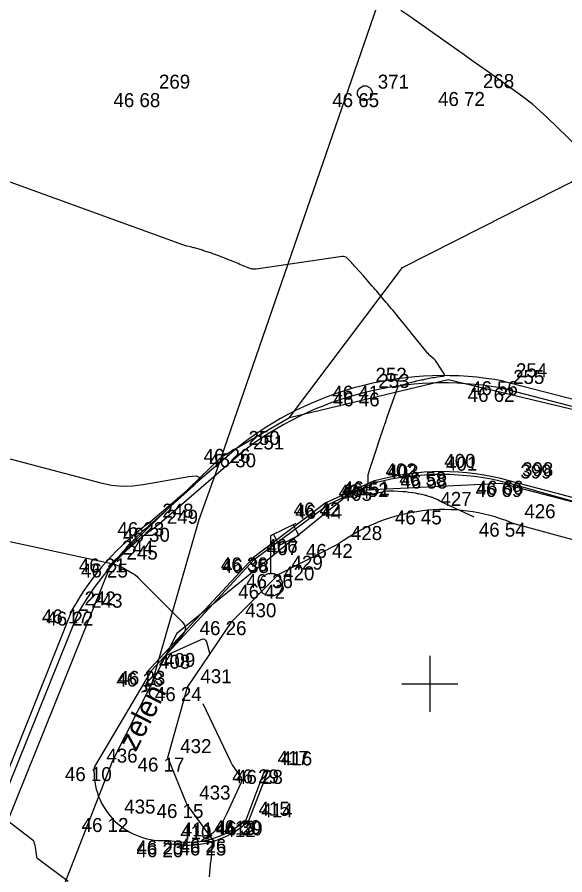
# Model space of a CAD drawing. Extents: x -702257 to -701487, y -1009871 to -1008841.
# Drawn here: x -701657.37 to -701647.59, y -1009053.42 to -1009038.08 of the extents above; entities that cross this region are included whole.
import ezdxf

# ---------------------------------------------------------------- set-up
doc = ezdxf.new("R2010")
doc.units = 0
for name, color, linetype in [('Ex_Major Contours', 7, 'Continuous'), ('Ex_Minor Contours', 7, 'Continuous'), ('Z_body', 7, 'Continuous'), ('Z_body_cisla', 7, 'Continuous'), ('Z_body_vysky_redukovane', 7, 'Continuous'), ('Z_hektometricka_sit', 7, 'Continuous'), ('Z_katastr_hranice', 7, 'Continuous'), ('Z_komunikace', 7, 'Continuous'), ('Z_obruba', 7, 'Continuous'), ('Z_popisy', 7, 'Continuous'), ('Z_site_vo_znaky', 7, 'Continuous'), ('Z_site_vodovod_znaky', 7, 'Continuous'), ('Z_zelen_obvod', 7, 'Continuous')]:
    doc.layers.add(name, color=color, linetype=linetype)

# ---------------------------------------------------------------- blocks, each defined once
blk = doc.blocks.new('POINT_DISPLAY')
blk.add_line((0, 0), (0, 0))
blk = doc.blocks.new('Z13')
for p, q in [((0, 0.88), (0.45, 1.1)), ((0.4, 1.07), (0.5, 0.88)), ((0, 0.2), (0, 0.88)), ((0.15, 0.7), (0.05, 0.9)), ((0.5, 0.88), (0.15, 0.7)), ((-0.15, 0.15), (-0.05, 0.2)), ((-0.05, 0.2), (0.05, 0.2)), ((0.05, 0.2), (0.15, 0.15)), ((-0.2, 0.05), (-0.15, 0.15)), ((-0.2, -0.05), (-0.2, 0.05)), ((0.15, 0.15), (0.2, 0.05)), ((0.2, 0.05), (0.2, -0.05)), ((-0.15, -0.15), (-0.2, -0.05)), ((-0.05, -0.2), (-0.15, -0.15)), ((0.15, -0.15), (0.05, -0.2)), ((0.2, -0.05), (0.15, -0.15)), ((0.05, -0.2), (-0.05, -0.2))]:
    blk.add_line(p, q)
blk = doc.blocks.new('Z614')
for p, q in [((-0.13, 0.03), (-0.1, 0.08)), ((-0.13, -0.03), (-0.13, 0.03)), ((-0.1, 0.08), (-0.08, 0.1)), ((-0.08, 0.1), (-0.03, 0.13)), ((-0.03, 0.13), (0.03, 0.13)), ((0.03, 0.13), (0.08, 0.1)), ((0.08, 0.1), (0.1, 0.08)), ((0.1, 0.08), (0.13, 0.03)), ((0.13, 0.03), (0.13, -0.03)), ((-0.1, -0.08), (-0.13, -0.03)), ((-0.08, -0.1), (-0.1, -0.08)), ((-0.03, -0.13), (-0.08, -0.1)), ((0.03, -0.13), (-0.03, -0.13)), ((0.08, -0.1), (0.03, -0.13)), ((0.1, -0.08), (0.08, -0.1)), ((0.13, -0.03), (0.1, -0.08))]:
    blk.add_line(p, q)

msp = doc.modelspace()

# ---------------------------------------------------------------- linework, layer by layer
at = {"layer": 'Ex_Major Contours'}
msp.add_lwpolyline([(-701656.465, -1009053.532), (-701657.004, -1009053.131), (-701657.012, -1009053.124), (-701657.018, -1009053.115), (-701657.023, -1009053.105), (-701657.025, -1009053.094), (-701657.03, -1009053.044), (-701657.031, -1009053.034), (-701657.032, -1009053.023), (-701657.034, -1009053.013), (-701657.035, -1009053.003), (-701657.042, -1009052.958), (-701657.043, -1009052.95), (-701657.044, -1009052.941), (-701657.046, -1009052.932), (-701657.048, -1009052.924), (-701657.055, -1009052.886), (-701657.058, -1009052.872), (-701657.062, -1009052.858), (-701657.069, -1009052.831), (-701657.072, -1009052.824), (-701657.075, -1009052.818), (-701657.079, -1009052.813), (-701657.084, -1009052.808), (-701657.686, -1009052.349)], dxfattribs=at)
at = {"layer": 'Ex_Minor Contours'}
for points in [[(-701646.975, -1009040.775), (-701647.911, -1009039.87), (-701648.034, -1009039.756), (-701648.161, -1009039.646), (-701648.292, -1009039.541), (-701648.427, -1009039.441), (-701648.974, -1009039.049), (-701649.111, -1009038.952), (-701649.248, -1009038.854), (-701649.385, -1009038.757), (-701649.522, -1009038.659), (-701650.336, -1009038.083), (-701650.519, -1009037.965)], [(-701649.207, -1009047.022), (-701649.797, -1009046.746), (-701649.805, -1009046.742), (-701649.812, -1009046.738), (-701649.82, -1009046.734), (-701649.827, -1009046.73), (-701649.857, -1009046.714), (-701649.864, -1009046.71), (-701649.871, -1009046.706), (-701649.879, -1009046.702), (-701649.887, -1009046.699), (-701649.932, -1009046.68), (-701649.942, -1009046.675), (-701649.952, -1009046.671), (-701649.963, -1009046.668), (-701649.973, -1009046.664), (-701650.036, -1009046.644), (-701650.05, -1009046.64), (-701650.064, -1009046.636), (-701650.078, -1009046.632), (-701650.093, -1009046.629), (-701650.179, -1009046.609), (-701650.199, -1009046.605), (-701650.218, -1009046.602), (-701650.237, -1009046.598), (-701650.257, -1009046.595), (-701650.377, -1009046.578), (-701650.403, -1009046.575), (-701650.43, -1009046.571), (-701650.456, -1009046.569), (-701650.483, -1009046.567), (-701650.646, -1009046.555), (-701650.682, -1009046.554), (-701650.718, -1009046.555), (-701650.754, -1009046.558), (-701650.79, -1009046.564), (-701651.083, -1009046.621), (-701651.099, -1009046.622), (-701651.114, -1009046.619), (-701651.127, -1009046.611), (-701651.138, -1009046.598), (-701651.184, -1009046.528), (-701651.189, -1009046.518), (-701651.19, -1009046.508), (-701651.187, -1009046.499), (-701651.18, -1009046.491), (-701651.131, -1009046.445), (-701651.123, -1009046.438), (-701651.109, -1009046.427), (-701651.106, -1009046.424), (-701651.105, -1009046.422), (-701651.104, -1009046.418), (-701651.103, -1009046.415), (-701651.103, -1009046.278), (-701651.103, -1009046.273), (-701651.102, -1009046.268), (-701651.101, -1009046.263), (-701651.1, -1009046.259), (-701651.092, -1009046.231), (-701651.089, -1009046.222), (-701651.077, -1009046.183), (-701651.07, -1009046.162), (-701651.047, -1009046.09), (-701651.035, -1009046.054), (-701650.935, -1009045.749), (-701650.923, -1009045.712), (-701650.911, -1009045.675), (-701650.899, -1009045.638), (-701650.886, -1009045.601), (-701650.828, -1009045.431), (-701650.82, -1009045.406), (-701650.811, -1009045.381), (-701650.803, -1009045.356), (-701650.794, -1009045.331), (-701650.759, -1009045.232), (-701650.741, -1009045.182), (-701650.724, -1009045.132), (-701650.571, -1009044.697), (-701650.565, -1009044.681), (-701650.563, -1009044.678), (-701650.561, -1009044.677), (-701650.373, -1009044.622), (-701650.35, -1009044.616), (-701650.327, -1009044.61), (-701650.281, -1009044.598), (-701650.269, -1009044.595), (-701650.258, -1009044.592), (-701650.246, -1009044.589), (-701650.235, -1009044.586), (-701650.155, -1009044.568), (-701650.138, -1009044.565), (-701650.121, -1009044.561), (-701650.104, -1009044.557), (-701650.087, -1009044.554), (-701649.949, -1009044.527), (-701649.936, -1009044.524), (-701649.923, -1009044.522), (-701649.889, -1009044.516), (-701649.869, -1009044.513), (-701649.761, -1009044.498), (-701649.744, -1009044.494), (-701649.736, -1009044.485), (-701649.735, -1009044.474), (-701649.742, -1009044.458), (-701649.872, -1009044.258), (-701649.884, -1009044.24), (-701649.898, -1009044.223), (-701649.912, -1009044.207), (-701649.928, -1009044.192), (-701649.993, -1009044.134), (-701650.009, -1009044.12), (-701650.024, -1009044.104), (-701650.038, -1009044.088), (-701650.052, -1009044.072), (-701650.332, -1009043.724), (-701650.37, -1009043.677), (-701650.409, -1009043.629), (-701650.448, -1009043.582), (-701650.486, -1009043.535), (-701650.657, -1009043.328), (-701650.688, -1009043.29), (-701650.72, -1009043.252), (-701650.751, -1009043.214), (-701650.783, -1009043.176), (-701650.923, -1009043.011), (-701650.949, -1009042.98), (-701650.975, -1009042.95), (-701651.001, -1009042.92), (-701651.027, -1009042.889), (-701651.185, -1009042.708), (-701651.187, -1009042.706), (-701651.327, -1009042.551), (-701651.346, -1009042.531), (-701651.364, -1009042.511), (-701651.383, -1009042.491), (-701651.401, -1009042.471), (-701651.476, -1009042.392), (-701651.496, -1009042.375), (-701651.518, -1009042.364), (-701651.542, -1009042.359), (-701651.567, -1009042.36), (-701653.104, -1009042.585), (-701653.141, -1009042.588), (-701653.177, -1009042.585), (-701653.212, -1009042.578), (-701653.247, -1009042.566), (-701653.393, -1009042.501), (-701653.423, -1009042.489), (-701653.453, -1009042.476), (-701653.482, -1009042.464), (-701653.512, -1009042.452), (-701653.64, -1009042.4), (-701653.665, -1009042.39), (-701653.691, -1009042.38), (-701653.717, -1009042.37), (-701653.743, -1009042.36), (-701653.854, -1009042.32), (-701653.877, -1009042.311), (-701653.899, -1009042.304), (-701653.922, -1009042.296), (-701653.945, -1009042.288), (-701654.042, -1009042.257), (-701654.062, -1009042.25), (-701654.081, -1009042.244), (-701654.101, -1009042.238), (-701654.121, -1009042.232), (-701654.206, -1009042.208), (-701654.223, -1009042.203), (-701654.24, -1009042.199), (-701654.258, -1009042.195), (-701654.275, -1009042.19), (-701654.345, -1009042.174), (-701654.362, -1009042.17), (-701654.38, -1009042.165), (-701654.397, -1009042.159), (-701654.414, -1009042.153), (-701658.244, -1009040.763)], [(-701660.105, -1009045.292), (-701655.877, -1009046.408), (-701655.689, -1009046.447), (-701655.5, -1009046.465), (-701655.31, -1009046.463), (-701655.12, -1009046.439), (-701654.306, -1009046.295), (-701654.176, -1009046.284), (-701654.119, -1009046.308), (-701654.135, -1009046.367), (-701654.224, -1009046.462), (-701654.96, -1009047.123), (-701654.977, -1009047.139), (-701654.994, -1009047.154), (-701655.028, -1009047.185), (-701655.036, -1009047.193), (-701655.045, -1009047.201), (-701655.054, -1009047.208), (-701655.062, -1009047.216), (-701655.147, -1009047.285), (-701655.16, -1009047.296), (-701655.173, -1009047.307), (-701655.185, -1009047.319), (-701655.196, -1009047.331), (-701655.245, -1009047.381), (-701655.255, -1009047.392), (-701655.266, -1009047.403), (-701655.277, -1009047.414), (-701655.288, -1009047.425), (-701655.333, -1009047.467), (-701655.345, -1009047.478), (-701655.355, -1009047.489), (-701655.366, -1009047.5), (-701655.376, -1009047.512), (-701655.471, -1009047.625), (-701655.481, -1009047.636), (-701655.491, -1009047.648), (-701655.513, -1009047.671), (-701655.518, -1009047.677), (-701655.523, -1009047.683), (-701655.528, -1009047.689), (-701655.533, -1009047.695), (-701655.65, -1009047.849), (-701655.65, -1009047.853), (-701655.502, -1009047.918), (-701655.478, -1009047.929), (-701655.454, -1009047.941), (-701655.43, -1009047.954), (-701655.406, -1009047.967), (-701655.306, -1009048.027), (-701655.282, -1009048.042), (-701655.26, -1009048.059), (-701655.238, -1009048.077), (-701655.217, -1009048.097), (-701654.423, -1009048.893), (-701654.382, -1009048.947), (-701654.367, -1009049.001), (-701654.377, -1009049.057), (-701654.413, -1009049.114), (-701654.689, -1009049.447), (-701654.698, -1009049.458), (-701654.707, -1009049.469), (-701654.725, -1009049.492), (-701654.728, -1009049.497), (-701654.728, -1009049.499), (-701654.725, -1009049.499), (-701654.72, -1009049.497), (-701654.083, -1009049.208), (-701654.051, -1009049.199), (-701654.025, -1009049.203), (-701654.006, -1009049.22), (-701653.993, -1009049.25), (-701653.93, -1009049.47)], [(-701654.054, -1009050.354), (-701653.56, -1009051.391), (-701653.542, -1009051.425), (-701653.524, -1009051.458), (-701653.503, -1009051.49), (-701653.482, -1009051.522), (-701653.392, -1009051.645), (-701653.374, -1009051.677), (-701653.366, -1009051.709), (-701653.368, -1009051.742), (-701653.379, -1009051.777), (-701653.629, -1009052.319), (-701653.64, -1009052.343), (-701653.651, -1009052.367), (-701653.674, -1009052.415), (-701653.68, -1009052.426), (-701653.686, -1009052.438), (-701653.693, -1009052.449), (-701653.7, -1009052.46), (-701653.735, -1009052.513), (-701653.743, -1009052.525), (-701653.752, -1009052.537), (-701653.761, -1009052.549), (-701653.771, -1009052.56), (-701653.819, -1009052.613), (-701653.831, -1009052.626), (-701653.843, -1009052.637), (-701653.855, -1009052.649), (-701653.868, -1009052.66), (-701653.932, -1009052.712), (-701653.947, -1009052.723), (-701653.963, -1009052.735), (-701653.979, -1009052.745), (-701653.995, -1009052.755), (-701654.074, -1009052.802), (-701654.082, -1009052.807), (-701654.084, -1009052.811), (-701654.08, -1009052.813), (-701654.071, -1009052.814), (-701654.016, -1009052.813), (-701654.006, -1009052.813), (-701653.996, -1009052.813), (-701653.986, -1009052.814), (-701653.976, -1009052.814), (-701653.917, -1009052.819), (-701653.909, -1009052.819), (-701653.89, -1009052.819), (-701653.89, -1009052.82), (-701653.91, -1009053.124), (-701653.911, -1009053.133), (-701653.912, -1009053.141), (-701653.913, -1009053.15), (-701653.915, -1009053.159), (-701653.921, -1009053.194), (-701653.922, -1009053.203), (-701653.923, -1009053.212), (-701653.925, -1009053.221), (-701653.925, -1009053.23), (-701653.945, -1009053.453)]]:
    msp.add_lwpolyline(points, dxfattribs=at)
at = {"layer": 'Z_hektometricka_sit'}
for p, q in [((-701650, -1009049.5), (-701650, -1009050.5)), ((-701650, -1009049.5), (-701650, -1009050.5)), ((-701650.5, -1009050), (-701649.5, -1009050)), ((-701650.5, -1009050), (-701649.5, -1009050))]:
    msp.add_line(p, q, dxfattribs=at)
at = {"layer": 'Z_katastr_hranice'}
for p, q in [((-701653.72, -1009045.94), (-701645.42, -1009021.86)), ((-701650.49, -1009042.56), (-701647.04, -1009040.81)), ((-701652.51, -1009045.24), (-701650.49, -1009042.56)), ((-701652.51, -1009045.24), (-701649.67, -1009044.56)), ((-701649.67, -1009044.56), (-701641.86, -1009046.44)), ((-701653.72, -1009045.94), (-701652.51, -1009045.24)), ((-701666.43, -1009045.51), (-701655.69, -1009047.85)), ((-701655.69, -1009047.85), (-701653.72, -1009045.94)), ((-701653.72, -1009045.94), (-701654.13, -1009047.07)), ((-701648.72, -1009046.42), (-701651.37, -1009046.55)), ((-701642.28, -1009048.09), (-701648.72, -1009046.42)), ((-701651.37, -1009046.55), (-701654.52, -1009049.1)), ((-701654.13, -1009047.07), (-701654.97, -1009049.99)), ((-701664.86, -1009070.6), (-701655.69, -1009047.85)), ((-701654.52, -1009049.1), (-701654.97, -1009049.99)), ((-701654.97, -1009049.99), (-701655.67, -1009051.38)), ((-701655.67, -1009051.38), (-701657.22, -1009055.35))]:
    msp.add_line(p, q, dxfattribs=at)
at = {"layer": 'Z_komunikace'}
for p, q in [((-701648.68, -1009044.59), (-701641.92, -1009046.35)), ((-701653.46, -1009045.8), (-701655, -1009047.11)), ((-701656.39, -1009048.67), (-701658.88, -1009054.88))]:
    msp.add_line(p, q, dxfattribs=at)
for centre, major_axis, ratio, start_param, end_param in [((-701649.752, -1009050.4), (-1.421, 5.737), 0.998154, 5.85723, 6.719509), ((-701652.145, -1009051.04), (-4.378, -2.134), 0.997151, 4.886498, 5.319013)]:
    msp.add_ellipse(centre, major_axis=major_axis, ratio=ratio, start_param=start_param, end_param=end_param, dxfattribs=at)
at = {"layer": 'Z_obruba'}
for p, q in [((-701641.95, -1009046.47), (-701648.74, -1009044.71)), ((-701654.92, -1009047.21), (-701653.38, -1009045.88)), ((-701651.85, -1009046.76), (-701651.01, -1009046.38)), ((-701650.99, -1009046.41), (-701651.82, -1009046.8)), ((-701648.6, -1009046.41), (-701646.83, -1009046.91)), ((-701646.81, -1009046.84), (-701648.58, -1009046.37)), ((-701651.85, -1009046.76), (-701653.15, -1009047.74)), ((-701653.13, -1009047.77), (-701651.82, -1009046.8)), ((-701653.15, -1009047.74), (-701655.06, -1009049.8)), ((-701654.98, -1009049.77), (-701653.13, -1009047.77)), ((-701658.79, -1009054.94), (-701656.27, -1009048.71)), ((-701654.98, -1009049.77), (-701656, -1009051.49)), ((-701655.06, -1009049.8), (-701654.98, -1009049.77)), ((-701652.95, -1009051.53), (-701653.29, -1009052.44)), ((-701653.24, -1009052.46), (-701652.88, -1009051.54)), ((-701654.68, -1009052.85), (-701654.66, -1009052.8))]:
    msp.add_line(p, q, dxfattribs=at)
for centre, major_axis, ratio, start_param, end_param in [((-701649.751, -1009050.494), (-1.031, 5.782), 0.99776, 5.933119, 6.774216), ((-701649.769, -1009050.679), (-2.027, 3.989), 0.997622, 5.542645, 6.09371), ((-701649.827, -1009051.003), (-3.857, -2.802), 0.992757, 3.826656, 4.334624), ((-701652.38, -1009050.878), (-1.6, -4.185), 0.993971, 4.115383, 4.570102), ((-701654.772, -1009051.566), (0.197, -1.223), 0.993274, 4.492315, 6.213696), ((-701654.346, -1009051.225), (-0.089, -1.657), 0.997989, 6.133484, 7.06771), ((-701654.338, -1009051.251), (1.311, -0.891), 0.997858, 5.103635, 6.031122)]:
    msp.add_ellipse(centre, major_axis=major_axis, ratio=ratio, start_param=start_param, end_param=end_param, dxfattribs=at)
at = {"layer": 'Z_zelen_obvod'}
for p, q in [((-701648.54, -1009047.12), (-701646.62, -1009047.65)), ((-701652.7, -1009048.04), (-701651.63, -1009047.5)), ((-701653.53, -1009048.88), (-701652.7, -1009048.04)), ((-701654.33, -1009050.06), (-701653.53, -1009048.88)), ((-701654.68, -1009051.32), (-701654.33, -1009050.06)), ((-701654.34, -1009052.15), (-701654.68, -1009051.32)), ((-701653.89, -1009052.77), (-701654.34, -1009052.15))]:
    msp.add_line(p, q, dxfattribs=at)
msp.add_ellipse((-701649.753, -1009050.08), major_axis=(-2.726, -1.684), ratio=0.995771, start_param=3.772026, end_param=4.787538, dxfattribs=at)

# ---------------------------------------------------------------- block references
at = {"layer": 'Z_body'}
for p in [(-701655.07, -1009039.44), (-701651.16, -1009039.44), (-701649.27, -1009039.42), (-701651.2, -1009044.67), (-701648.74, -1009044.71), (-701648.68, -1009044.59), (-701651.15, -1009044.79), (-701653.46, -1009045.8), (-701653.38, -1009045.88), (-701649.96, -1009046.21), (-701649.94, -1009046.26), (-701651.01, -1009046.38), (-701650.99, -1009046.41), (-701648.6, -1009046.41), (-701648.58, -1009046.37), (-701651.85, -1009046.76), (-701651.82, -1009046.8), (-701650.04, -1009046.9), (-701655, -1009047.11), (-701648.54, -1009047.12), (-701654.92, -1009047.21), (-701651.63, -1009047.5), (-701655.73, -1009047.76), (-701653.15, -1009047.74), (-701653.13, -1009047.77), (-701655.65, -1009047.85), (-701652.7, -1009048.04), (-701652.84, -1009048.23), (-701656.39, -1009048.67), (-701656.27, -1009048.71), (-701653.53, -1009048.88), (-701654.98, -1009049.77), (-701655.06, -1009049.8), (-701654.33, -1009050.06), (-701654.68, -1009051.32), (-701656, -1009051.49), (-701652.95, -1009051.53), (-701652.88, -1009051.54), (-701654.34, -1009052.15), (-701655.68, -1009052.4), (-701653.29, -1009052.44), (-701653.24, -1009052.46), (-701654.68, -1009052.85), (-701654.66, -1009052.8), (-701653.89, -1009052.77), (-701653.89, -1009052.82)]:
    msp.add_blockref('POINT_DISPLAY', p, dxfattribs=at)
at = {"layer": 'Z_site_vo_znaky'}
msp.add_blockref('Z13', (-701652.84, -1009048.23), dxfattribs=at)
at = {"layer": 'Z_site_vodovod_znaky'}
msp.add_blockref('Z614', (-701651.16, -1009039.44), dxfattribs=at)

# ---------------------------------------------------------------- texts
at = {"layer": 'Z_body_cisla'}
for s, p in [('269', (-701654.84, -1009039.36)), ('371', (-701650.93, -1009039.36)), ('268', (-701649.05, -1009039.35)), ('254', (-701648.46, -1009044.52)), ('252', (-701650.97, -1009044.6)), ('255', (-701648.51, -1009044.64)), ('253', (-701650.92, -1009044.71)), ('250', (-701653.24, -1009045.73)), ('251', (-701653.16, -1009045.81)), ('400', (-701649.74, -1009046.14)), ('401', (-701649.71, -1009046.19)), ('402', (-701650.79, -1009046.31)), ('403', (-701650.76, -1009046.33)), ('399', (-701648.38, -1009046.33)), ('398', (-701648.35, -1009046.29)), ('404', (-701651.63, -1009046.69)), ('405', (-701651.59, -1009046.73)), ('427', (-701649.81, -1009046.82)), ('248', (-701654.78, -1009047.03)), ('426', (-701648.31, -1009047.04)), ('249', (-701654.7, -1009047.14)), ('428', (-701651.41, -1009047.43)), ('244', (-701655.5, -1009047.69)), ('406', (-701652.92, -1009047.66)), ('407', (-701652.91, -1009047.7)), ('245', (-701655.42, -1009047.78)), ('429', (-701652.47, -1009047.96)), ('420', (-701652.62, -1009048.15)), ('242', (-701656.17, -1009048.6)), ('243', (-701656.05, -1009048.64)), ('430', (-701653.3, -1009048.81)), ('408', (-701654.84, -1009049.73)), ('409', (-701654.75, -1009049.7)), ('431', (-701654.1, -1009049.99)), ('432', (-701654.46, -1009051.24)), ('436', (-701655.78, -1009051.41)), ('417', (-701652.72, -1009051.45)), ('416', (-701652.66, -1009051.46)), ('433', (-701654.12, -1009052.07)), ('435', (-701655.46, -1009052.32)), ('415', (-701653.06, -1009052.36)), ('414', (-701653.01, -1009052.39)), ('410', (-701654.46, -1009052.78)), ('411', (-701654.43, -1009052.73)), ('413', (-701653.67, -1009052.7)), ('412', (-701653.67, -1009052.74))]:
    msp.add_text(s, height=0.25, dxfattribs=at).set_placement(p)
at = {"layer": 'Z_body_vysky_redukovane'}
for s, p in [('46 68', (-701655.653, -1009039.69)), ('46 65', (-701651.743, -1009039.69)), ('46 72', (-701649.853, -1009039.67)), ('46 41', (-701651.742, -1009044.92)), ('46 62', (-701649.323, -1009044.96)), ('46 56', (-701649.263, -1009044.84)), ('46 46', (-701651.733, -1009045.04)), ('46 26', (-701654.043, -1009046.05)), ('46 30', (-701653.943, -1009046.13)), ('46 58', (-701650.543, -1009046.46)), ('46 58', (-701650.523, -1009046.51)), ('46 52', (-701651.573, -1009046.66)), ('46 51', (-701651.552, -1009046.63)), ('46 69', (-701649.183, -1009046.66)), ('46 66', (-701649.163, -1009046.62)), ('46 42', (-701652.433, -1009047.01)), ('46 44', (-701652.403, -1009047.05)), ('46 45', (-701650.623, -1009047.15)), ('46 23', (-701655.583, -1009047.36)), ('46 54', (-701649.123, -1009047.37)), ('46 30', (-701655.483, -1009047.46)), ('46 42', (-701652.213, -1009047.75)), ('46 21', (-701656.272, -1009048.01)), ('46 36', (-701653.733, -1009047.99)), ('46 38', (-701653.713, -1009048.02)), ('46 25', (-701656.233, -1009048.1)), ('46 36', (-701653.283, -1009048.29)), ('46 42', (-701653.423, -1009048.48)), ('46 17', (-701656.932, -1009048.92)), ('46 22', (-701656.853, -1009048.96)), ('46 26', (-701654.113, -1009049.13)), ('46 18', (-701655.602, -1009050.05)), ('46 23', (-701655.563, -1009050.02)), ('46 24', (-701654.913, -1009050.31)), ('46 17', (-701655.222, -1009051.57)), ('46 10', (-701656.521, -1009051.74)), ('46 29', (-701653.533, -1009051.78)), ('46 28', (-701653.463, -1009051.79)), ('46 15', (-701654.882, -1009052.4)), ('46 12', (-701656.222, -1009052.65)), ('46 30', (-701653.853, -1009052.69)), ('46 29', (-701653.823, -1009052.71)), ('46 23', (-701655.243, -1009053.05)), ('46 20', (-701655.243, -1009053.1)), ('46 26', (-701654.473, -1009053.02)), ('46 25', (-701654.473, -1009053.07))]:
    msp.add_text(s, height=0.25, dxfattribs=at).set_placement(p)
at = {"layer": 'Z_popisy'}
msp.add_text('zeleň', height=0.38, rotation=63, dxfattribs=at).set_placement((-701655.25, -1009051.222))

doc.saveas('drawing.dxf')
